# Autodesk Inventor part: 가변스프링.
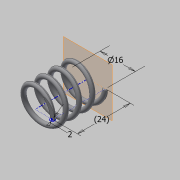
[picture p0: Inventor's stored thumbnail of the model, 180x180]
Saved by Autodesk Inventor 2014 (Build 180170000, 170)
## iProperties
Created: 2015-04
Part Number: 가변스프링.
Material: Generic
Document SubType Name: Modeling
Designer: Administrator
Density: 1 g/cm^3
Appearance: Default
Mass: 0.62043 g
Surface Area: 12.6362 cm^2
Volume: 0.62043 cm^3
Author: Administrator
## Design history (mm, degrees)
sketch "스케치1"
  geometry: L1 (0, 0)-(8, 0); L2 (8, 0)-(8, 24); L3 (8, 24)-(0, 24); L4 (0, 24)-(0, 0); C1 r 1 at (8, 0)
  constraints: 8 end point, 2 parallel, 1 centre point, 1 coincident, 1 horizontal, 1 perpendicular
  dimensions: "d0" = 16 diameter of L2 L4; "d1" = 24 distance between parallel lines of L1 L3 (derived); "d2" = 2 diameter of C1
feature "코일1" pitch "d3" = 10; turns "d5" = 4; dims "d4" = 24 (= d1), "d6" = 0, angle "d7" = 90 deg, angle "d8" = 90 deg, "d9" = 0, "d10" = 0
sketch "스케치2"
  geometry: L1 (-7, 0)-(-9, 0) reference; 1 further point
  constraints: 1 horizontal alignment
extrude "돌출1" cut sketch "스케치2" stored distance "d11" = 10; taper "d12" = 0 deg
node "작업 평면1"
sketch "스케치3"
  geometry: L1 (7, 0)-(9, 0) reference; 1 further point
  constraints: 1 horizontal alignment
extrude "돌출2" cut sketch "스케치3" stored distance "d13" = 10; taper "d14" = 0 deg
node "솔리드1"
node "절단 모서리 투영1"
node "절단 모서리 투영2"
